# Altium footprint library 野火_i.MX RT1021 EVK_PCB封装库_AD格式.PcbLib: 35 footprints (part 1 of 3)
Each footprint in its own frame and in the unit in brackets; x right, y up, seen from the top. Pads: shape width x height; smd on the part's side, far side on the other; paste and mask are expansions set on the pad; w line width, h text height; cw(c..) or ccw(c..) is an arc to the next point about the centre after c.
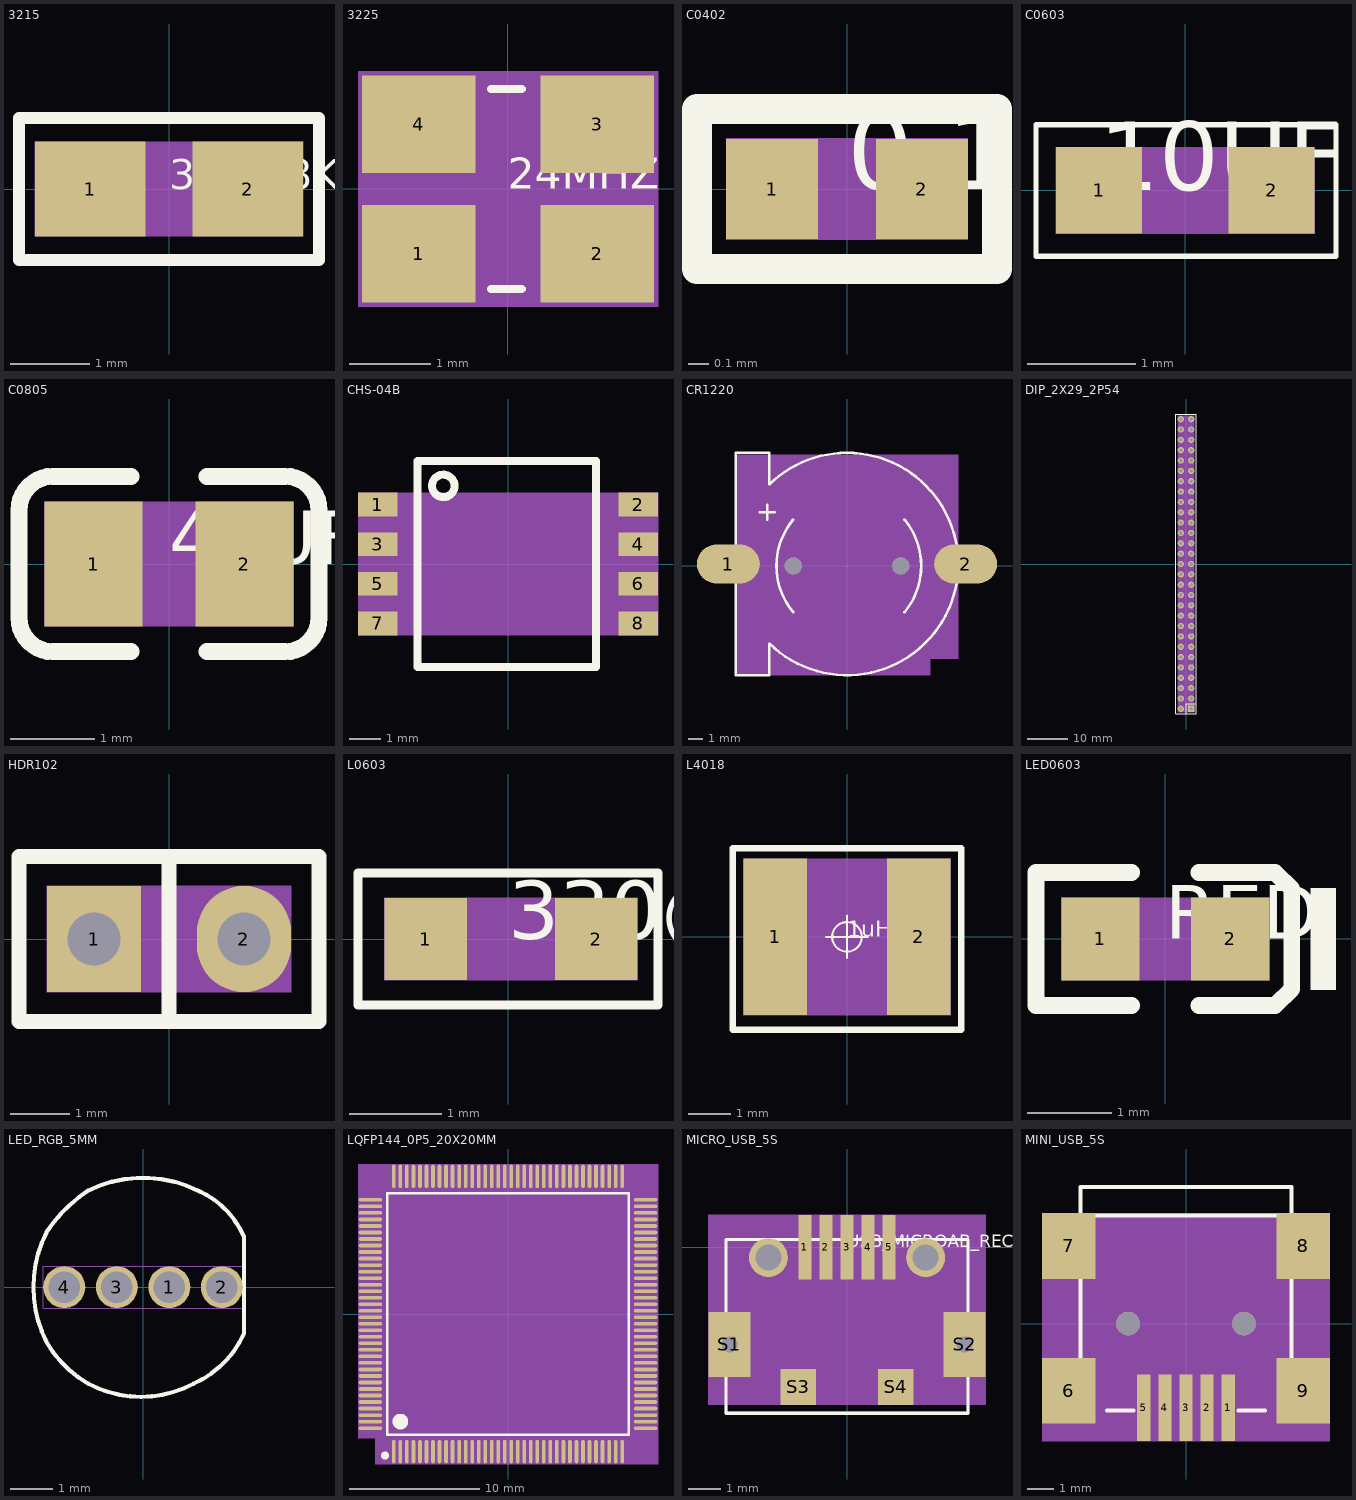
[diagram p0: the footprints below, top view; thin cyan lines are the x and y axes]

## 3215 [mm] "3215"
pads (2):
  rect 1.4x1.2 smd: 1(-1,0) 2(1,0)
Top Overlay:
  lines w0.15: -1.9,-0.9 1.9,-0.9 1.9,0.9 -1.9,0.9 -1.9,-0.9
  text "32.768KHZ" at 0,0 h0.38
Mechanical 6:
  text "1" at -1,0.152 h0.38
  text "2" at 1,0.152 h0.38
Mechanical 7:
  region: -1.7,-0.6 1.7,-0.6 1.7,0.6 -1.7,0.6
3D body: height 3.81, standoff 0, extent -1.7,-0.6 1.7,0.6

## 3225 [mil] "3225"
pads (4):
  rect 55.12x47.24 smd: 1(-43.3,-31.5) 2(43.31,-31.5) 3(43.31,31.49) 4(-43.3,31.49)
Top Overlay:
  lines w3.94: -8.3,-48.51 6.7,-48.51 ; -8.3,48.51 6.7,48.51
  text "24MHZ" at 0,0 h15
Mechanical 6:
  text "3" at 43.31,25.49 h15
  text "1" at -43.3,-37.5 h15
  text "4" at -43.3,25.49 h15
  text "2" at 43.31,-37.5 h15
Mechanical 7:
  region: -72.83,-57.09 72.84,-57.09 72.84,57.08 -72.83,57.08
3D body: height 150, standoff 0, extent -72.83,-57.09 72.84,57.08

## C0402 [mm] "C0402"
pads (2):
  rect 0.46x0.5 smd: 1(-0.375,0) 2(0.375,0)
Top Overlay:
  lines w0.15: -0.75,-0.4 -0.75,0.4 0.75,0.4 0.75,-0.4 -0.75,-0.4
  text "0.1UF" at 0,0 h0.38
Mechanical 6:
  text "1" at -0.375,0.152 h0.38
  text "2" at 0.375,0.152 h0.38
Mechanical 7:
  region: -0.605,-0.255 0.605,-0.255 0.605,0.255 -0.605,0.255
3D body: height 3.81, standoff 0, extent -0.605,-0.255 0.605,0.255

## C0603 [mil] "C0603"
pads (2):
  rect 31.5x31.5 smd: 1(-31.5,0) 2(31.49,0)
Top Overlay:
  lines w2: -54.5,-24 55,-24 55,24 -54.5,24 -54.5,-24
  text "10UF" at -31.5,0 h25
Mechanical 6:
  text "1" at -31.5,-10 h25
  text "2" at 31.49,-10 h25
Mechanical 7:
  region: -47.25,-15.75 47.24,-15.75 47.24,15.75 -47.25,15.75
3D body: height 150, standoff 0, extent -47.25,-15.75 47.24,15.75

## C0805 [mm] "C0805"
pads (2):
  rect 1.16x1.47 smd: 1(-0.89,0) 2(0.89,0)
Top Overlay:
  lines w0.2: -0.45,-1.035 -1.37,-1.035 cw(c-1.37,-0.635) -1.77,-0.635 -1.77,0.635 cw(c-1.37,0.635) -1.37,1.035 -0.45,1.035 ; 0.45,-1.035 1.37,-1.035 ccw(c1.37,-0.635) 1.77,-0.635 1.77,0.635 ccw(c1.37,0.635) 1.37,1.035 0.45,1.035
  text "47UF" at 0,0 h0.64
Mechanical 6:
  text "2" at 0.89,-0.254 h0.64
  text "1" at -0.89,-0.254 h0.64
Mechanical 7:
  region: -1.47,-0.735 1.47,-0.735 1.47,0.735 -1.47,0.735
3D body: height 3.81, standoff 0, extent -1.47,-0.735 1.47,0.735

## CHS-04B [mil] "CHS-04B"
pads (8):
  rect 50x30 smd: 1(-164.37,75) 2(164.37,75) 3(-164.37,25) 4(164.37,25) 5(-164.37,-25) 6(164.37,-25) 7(-164.37,-75) 8(164.37,-75)
Top Overlay:
  circle w10: c-81.69,98.62 r14.19
  lines w10: -114.37,-130.12 -114.37,130.12 111.22,130.12 111.22,-130.12 -114.37,-130.12
Mechanical 6:
  text "7" at -164.37,-65 h25
  text "6" at 164.37,-15 h25
  text "5" at -164.37,-15 h25
  text "8" at 164.37,-65 h25
  text "4" at 164.37,35 h25
  text "3" at -164.37,35 h25
  text "2" at 164.37,85 h25
  text "1" at -164.37,85 h25
Mechanical 7:
  region: -189.37,-89.96 189.37,-89.96 189.37,89.96 -189.37,89.96
3D body: height 150, standoff 0, extent -189.37,-89.96 189.37,89.96

## CR1220 [mil] "CR1220"
pads (4):
  oval 169.29x106.3 smd: 1(-320,5) 2(320,5)
  round 46 / inner round 60 / far side round 46 hole 46: " "(-145,0) " "(145,0)
Top Overlay:
  lines w7: -235,145 -195,145 ; -215,125 -215,165 ; -145.19,-124.77 cw(c5,0) -145.09,124.89 ; 155,-125 ccw(c5,0) 155.09,124.89 ; 298.2,-27.8 cw(c0,5) -209.62,-209.61 -210,-295 -300,-295 -300,5 -300,305 -210,305 -209.62,219.61 cw(c0,5.01) 0,305 cw(c0,5) 298.2,37.8
Mechanical 6:
  text "1" at -310,5 h25
  text "2" at 330,5 h25
Mechanical 7:
  region: -300,-295 225,-295 225,-250 300,-250 300,300 -300,300
3D body: height 150, standoff 0, extent -300,-295 300,300

## DIP_2X29_2P54 [mil] "DIP_2X29_2P54"
pads (58):
  rect 60x60 / inner round 60 / far side rect 60x60 hole 35.43: 1(50,-1400)
  round 60 hole 35.43: 2(-50,-1400) 3(50,-1300) 4(-50,-1300) 5(50,-1200) 6(-50,-1200) 7(50,-1100) 8(-50,-1100) 9(50,-1000) 10(-50,-1000) 11(50,-900) 12(-50,-900) 13(50,-800) 14(-50,-800) 15(50,-700) 16(-50,-700) 17(50,-600) 18(-50,-600) 19(50,-500) 20(-50,-500) 21(50,-400) 22(-50,-400) 23(50,-300) 24(-50,-300) 25(50,-200) 26(-50,-200) 27(50,-100) 28(-50,-100) 29(50,0) 30(-50,0) 31(50,100) 32(-50,100) 33(50,200) 34(-50,200) 35(50,300) 36(-50,300) 37(50,400) 38(-50,400) 39(50,500) 40(-50,500) 41(50,600) 42(-50,600) 43(50,700) 44(-50,700) 45(50,800) 46(-50,800) 47(50,900) 48(-50,900) 49(50,1000) 50(-50,1000) 51(50,1100) 52(-50,1100) 53(50,1200) 54(-50,1200) 55(50,1300) 56(-50,1300) 57(50,1400) 58(-50,1400)
Top Overlay:
  lines w12: 0,-1450 0,-1350 100,-1350 ; -100,-1450 -100,1450 100,1450 100,-1450 -100,-1450
Mechanical 6:
  text "1" at 60,-1400 h25
  text "3" at 60,-1300 h25
  text "5" at 60,-1200 h25
  text "7" at 60,-1100 h25
  text "9" at 60,-1000 h25
  text "11" at 70,-900 h25
  text "13" at 70,-800 h25
  text "15" at 70,-700 h25
  text "18" at -30,-600 h25
  text "16" at -30,-700 h25
  text "12" at -30,-900 h25
  text "8" at -40,-1100 h25
  text "58" at -30,1400 h25
  text "57" at 70,1400 h25
  text "47" at 70,900 h25
  text "14" at -30,-800 h25
  text "22" at -30,-400 h25
  text "21" at 70,-400 h25
  text "48" at -30,900 h25
  text "45" at 70,800 h25
  text "46" at -30,800 h25
  text "43" at 70,700 h25
  text "41" at 70,600 h25
  text "44" at -30,700 h25
  text "39" at 70,500 h25
  text "38" at -30,400 h25
  text "37" at 70,400 h25
  text "36" at -30,300 h25
  text "35" at 70,300 h25
  text "42" at -30,600 h25
  text "40" at -30,500 h25
  text "10" at -30,-1000 h25
  text "19" at 70,-500 h25
  text "17" at 70,-600 h25
  text "6" at -40,-1200 h25
  text "4" at -40,-1300 h25
  text "33" at 70,200 h25
  text "20" at -30,-500 h25
  text "23" at 70,-300 h25
  text "50" at -30,1000 h25
  text "53" at 70,1200 h25
  text "54" at -30,1200 h25
  text "51" at 70,1100 h25
  text "52" at -30,1100 h25
  text "49" at 70,1000 h25
  text "26" at -30,-200 h25
  text "32" at -30,100 h25
  text "34" at -30,200 h25
  text "31" at 70,100 h25
  text "29" at 70,0 h25
  text "28" at -30,-100 h25
  text "27" at 70,-100 h25
  text "24" at -30,-300 h25
  text "25" at 70,-200 h25
  text "30" at -30,0 h25
  text "2" at -40,-1400 h25
  text "55" at 70,1300 h25
  text "56" at -30,1300 h25
Mechanical 7:
  region: -81,-1431 81,-1431 81,1431 -81,1431
3D body: height 150, standoff 0, extent -81,-1431 81,1431

## HDR102 [mil] "HDR102"
pads (2):
  rect 62.99x70.87 / inner round 60 / far side rect 62.99x70.87 hole 35.43: 1(-50,0)
  oval 62.99x70.87 / inner round 60 / far side oval 62.99x70.87 hole 35.43: 2(50,0)
Top Overlay:
  lines w10: 0,-55.12 0,55.12 ; -100,-55.12 100,-55.12 100,55.12 -100,55.12 -100,-55.12
Mechanical 6:
  text "2" at 50,-10 h25
  text "1" at -50,-10 h25
Mechanical 7:
  region: -81.5,-35.43 81.5,-35.43 81.5,35.43 -81.5,35.43
3D body: height 150, standoff 0, extent -81.5,-35.43 81.5,35.43

## L0603 [mil] "L0603"
pads (2):
  rect 35x35 smd: 1(-35,0) 2(37.49,0)
Top Overlay:
  lines w3.94: -63.74,-28 -63.74,28 63.74,28 63.74,-28 -63.74,-28
  text "330@100MHz" at 0,0 h25
Mechanical 6:
  text "2" at 37.49,-10 h25
  text "1" at -35,-10 h25
Mechanical 7:
  region: -52.5,-17.5 54.99,-17.5 54.99,17.5 -52.5,17.5
3D body: height 150, standoff 0, extent -52.5,-17.5 54.99,17.5

## L4018 [mm] "L4018"
pads (2):
  rect 1.5x3.7 smd: 1(-1.7,0) 2(1.7,0)
Top Overlay:
  circle w0.05: c0,0 r0.35
  lines w0.05: -0.5,0 0.5,0 ; 0,-0.5 0,0.5
  lines w0.152: -2.7,-2.2 -2.7,2.1 2.7,2.1 2.7,-2.2 -2.7,-2.2
  text "1uH" at 0,0 h0.38
Mechanical 6:
  text "1" at -1.7,0.152 h0.38
  text "2" at 1.7,0.152 h0.38
Mechanical 7:
  region: -2.45,-1.85 2.45,-1.85 2.45,1.85 -2.45,1.85
3D body: height 3.81, standoff 0, extent -2.45,-1.85 2.45,1.85

## LED0603 [mil] "LED0603"
pads (2):
  rect 36.61x38.58 smd: 1(-30.31,0) 2(30.32,0)
Top Overlay:
  pour cut-out: 67.91,-23.62 79.73,-23.62 79.73,23.62 67.91,23.62
  lines w7.87: -15.75,-31.1 -60.43,-31.1 -60.43,31.1 -15.75,31.1 ; 15.75,-31.1 51.18,-31.1 59.06,-23.5 59.06,23.5 51.18,31.1 15.75,31.1
  text "RED" at 0,0 h25
Mechanical 6:
  text "1" at -20.31,0 h25
  text "2" at 40.32,0 h25
Mechanical 7:
  region: -48.62,-19.29 48.62,-19.29 48.62,19.29 -48.62,19.29
3D body: height 150, standoff 0, extent -48.62,-19.29 48.62,19.29

## LED_RGB_5MM [mm] "LED_RGB_5MM"
pads (4):
  round 1 / inner round 1.524 / far side round 1 hole 0.75: 1(0.625,0) 2(1.875,0) 3(-0.625,0) 4(-1.875,0)
Top Overlay:
  lines w0.1: -2.3,-1.3 ccw(c0.05,0.05) -1.3,-2.3 ccw(c-0.05,0.05) 1.2,-2.3 ccw(c0.25,-0.15) 2.4,-1.1 2.4,1.2 ccw(c0.45,0.35) 1.3,2.3 ccw(c0,-0.35) -1.3,2.3 ccw(c0.65,-0.65) -2.3,1.3 ccw(c0.3,0) -2.3,-1.3
Mechanical 6:
  text "3" at -0.879,0 h0.64
  text "2" at 1.621,0 h0.64
  text "1" at 0.371,0 h0.64
  text "4" at -2.129,0 h0.64
Mechanical 7:
  lines w0.025: -2.375,-0.5 2.375,-0.5 2.375,0.5 -2.375,0.5 -2.375,-0.5

## LQFP144_0P5_20X20MM [mil] "LQFP144_0P5_20X20MM"
pads (144):
  oval 11.02x70.87 smd: 1(-344.49,-415.35) 2(-324.8,-415.35) 3(-305.12,-415.35) 4(-285.43,-415.35) 5(-265.75,-415.35) 6(-246.06,-415.35) 7(-226.38,-415.35) 8(-206.69,-415.35) 9(-187.01,-415.35) 10(-167.32,-415.35) 11(-147.64,-415.35) 12(-127.95,-415.35) 13(-108.27,-415.35) 14(-88.58,-415.35) 15(-68.9,-415.35) 16(-49.21,-415.35) 17(-29.53,-415.35) 18(-9.84,-415.35) 19(9.84,-415.35) 20(29.53,-415.35) 21(49.21,-415.35) 22(68.9,-415.35) 23(88.58,-415.35) 24(108.27,-415.35) 25(127.95,-415.35) 26(147.64,-415.35) 27(167.32,-415.35) 28(187.01,-415.35) 29(206.69,-415.35) 30(226.38,-415.35) 31(246.06,-415.35) 32(265.75,-415.35) 33(285.43,-415.35) 34(305.12,-415.35) 35(324.8,-415.35) 36(344.49,-415.35) 73(344.49,415.35) 74(324.8,415.35) 75(305.12,415.35) 76(285.43,415.35) 77(265.75,415.35) 78(246.06,415.35) 79(226.38,415.35) 80(206.69,415.35) 81(187.01,415.35) 82(167.32,415.35) 83(147.64,415.35) 84(127.95,415.35) 85(108.27,415.35) 86(88.58,415.35) 87(68.9,415.35) 88(49.21,415.35) 89(29.53,415.35) 90(9.84,415.35) 91(-9.84,415.35) 92(-29.53,415.35) 93(-49.21,415.35) 94(-68.9,415.35) 95(-88.58,415.35) 96(-108.27,415.35) 97(-127.95,415.35) 98(-147.64,415.35) 99(-167.32,415.35) 100(-187.01,415.35) 101(-206.69,415.35) 102(-226.38,415.35) 103(-246.06,415.35) 104(-265.75,415.35) 105(-285.43,415.35) 106(-305.12,415.35) 107(-324.8,415.35) 108(-344.49,415.35)
  oval 70.87x11.02 smd: 37(415.35,-344.49) 38(415.35,-324.8) 39(415.35,-305.12) 40(415.35,-285.43) 41(415.35,-265.75) 42(415.35,-246.06) 43(415.35,-226.38) 44(415.35,-206.69) 45(415.35,-187.01) 46(415.35,-167.32) 47(415.35,-147.64) 48(415.35,-127.95) 49(415.35,-108.27) 50(415.35,-88.58) 51(415.35,-68.9) 52(415.35,-49.21) 53(415.35,-29.53) 54(415.35,-9.84) 55(415.35,9.84) 56(415.35,29.53) 57(415.35,49.21) 58(415.35,68.9) 59(415.35,88.58) 60(415.35,108.27) 61(415.35,127.95) 62(415.35,147.64) 63(415.35,167.32) 64(415.35,187.01) 65(415.35,206.69) 66(415.35,226.38) 67(415.35,246.06) 68(415.35,265.75) 69(415.35,285.43) 70(415.35,305.12) 71(415.35,324.8) 72(415.35,344.49) 109(-415.35,344.49) 110(-415.35,324.8) 111(-415.35,305.12) 112(-415.35,285.43) 113(-415.35,265.75) 114(-415.35,246.06) 115(-415.35,226.38) 116(-415.35,206.69) 117(-415.35,187.01) 118(-415.35,167.32) 119(-415.35,147.64) 120(-415.35,127.95) 121(-415.35,108.27) 122(-415.35,88.58) 123(-415.35,68.9) 124(-415.35,49.21) 125(-415.35,29.53) 126(-415.35,9.84) 127(-415.35,-9.84) 128(-415.35,-29.53) 129(-415.35,-49.21) 130(-415.35,-68.9) 131(-415.35,-88.58) 132(-415.35,-108.27) 133(-415.35,-127.95) 134(-415.35,-147.64) 135(-415.35,-167.32) 136(-415.35,-187.01) 137(-415.35,-206.69) 138(-415.35,-226.38) 139(-415.35,-246.06) 140(-415.35,-265.75) 141(-415.35,-285.43) 142(-415.35,-305.12) 143(-415.35,-324.8) 144(-415.35,-344.49)
Top Overlay:
  circle w23.62: c-324.8,-324.8 r11.81
  circle w11.81: c-371.06,-427.17 r5.9
  lines w7.87: -364.17,-364.17 364.17,-364.17 364.17,364.17 -364.17,364.17 -364.17,-364.17
Mechanical 6:
  text "104" at -295.75,415.35 h25
  text "112" at -445.35,285.43 h25
  text "77" at 245.75,415.35 h25
  text "144" at -445.35,-344.49 h25
  text "11" at -167.64,-415.35 h25
  text "20" at 9.53,-415.35 h25
  text "29" at 186.69,-415.35 h25
  text "128" at -445.35,-29.53 h25
  text "83" at 127.64,415.35 h25
  text "84" at 107.95,415.35 h25
  text "87" at 48.9,415.35 h25
  text "88" at 29.21,415.35 h25
  text "89" at 9.53,415.35 h25
  text "90" at -10.16,415.35 h25
  text "91" at -29.84,415.35 h25
  text "92" at -49.53,415.35 h25
  text "76" at 265.43,415.35 h25
  text "78" at 226.06,415.35 h25
  text "80" at 186.69,415.35 h25
  text "81" at 167.01,415.35 h25
  text "59" at 395.35,88.58 h25
  text "115" at -445.35,226.38 h25
  text "41" at 395.35,-265.75 h25
  text "66" at 395.35,226.38 h25
  text "61" at 395.35,127.95 h25
  text "86" at 68.58,415.35 h25
  text "102" at -256.38,415.35 h25
  text "134" at -445.35,-147.64 h25
  text "5" at -275.75,-415.35 h25
  text "39" at 395.35,-305.12 h25
  text "31" at 226.06,-415.35 h25
  text "114" at -445.35,246.06 h25
  text "55" at 395.35,9.84 h25
  text "69" at 395.35,285.43 h25
  text "73" at 324.49,415.35 h25
  text "79" at 206.38,415.35 h25
  text "105" at -315.43,415.35 h25
  text "101" at -236.69,415.35 h25
  text "8" at -216.69,-415.35 h25
  text "4" at -295.43,-415.35 h25
  text "125" at -445.35,29.53 h25
  text "9" at -197.01,-415.35 h25
  text "123" at -445.35,68.9 h25
  text "124" at -445.35,49.21 h25
  text "10" at -187.32,-415.35 h25
  text "12" at -147.95,-415.35 h25
  text "13" at -128.27,-415.35 h25
  text "14" at -108.58,-415.35 h25
  text "15" at -88.9,-415.35 h25
  text "16" at -69.21,-415.35 h25
  text "117" at -445.35,187.01 h25
  text "118" at -445.35,167.32 h25
  text "119" at -445.35,147.64 h25
  text "120" at -445.35,127.95 h25
  text "121" at -445.35,108.27 h25
  text "122" at -445.35,88.58 h25
  text "17" at -49.53,-415.35 h25
  text "18" at -29.84,-415.35 h25
  text "116" at -445.35,206.69 h25
  text "3" at -315.12,-415.35 h25
  text "126" at -445.35,9.84 h25
  text "127" at -445.35,-9.84 h25
  text "7" at -236.38,-415.35 h25
  text "1" at -354.49,-415.35 h25
  text "2" at -334.8,-415.35 h25
  text "131" at -445.35,-88.58 h25
  text "132" at -445.35,-108.27 h25
  text "133" at -445.35,-127.95 h25
  text "136" at -445.35,-187.01 h25
  text "137" at -445.35,-206.69 h25
  text "138" at -445.35,-226.38 h25
  text "139" at -445.35,-246.06 h25
  text "140" at -445.35,-265.75 h25
  text "129" at -445.35,-49.21 h25
  text "130" at -445.35,-68.9 h25
  text "143" at -445.35,-324.8 h25
  text "141" at -445.35,-285.43 h25
  text "142" at -445.35,-305.12 h25
  text "42" at 395.35,-246.06 h25
  text "43" at 395.35,-226.38 h25
  text "45" at 395.35,-187.01 h25
  text "46" at 395.35,-167.32 h25
  text "48" at 395.35,-127.95 h25
  text "47" at 395.35,-147.64 h25
  text "50" at 395.35,-88.58 h25
  text "54" at 395.35,-9.84 h25
  text "53" at 395.35,-29.53 h25
  text "63" at 395.35,167.32 h25
  text "62" at 395.35,147.64 h25
  text "49" at 395.35,-108.27 h25
  text "36" at 324.49,-415.35 h25
  text "37" at 395.35,-344.49 h25
  text "58" at 395.35,68.9 h25
  text "57" at 395.35,49.21 h25
  text "67" at 395.35,246.06 h25
  text "68" at 395.35,265.75 h25
  text "56" at 395.35,29.53 h25
  text "72" at 395.35,344.49 h25
  text "65" at 395.35,206.69 h25
  text "38" at 395.35,-324.8 h25
  text "34" at 285.12,-415.35 h25
  text "52" at 395.35,-49.21 h25
  text "111" at -445.35,305.12 h25
  text "110" at -445.35,324.8 h25
  text "109" at -445.35,344.49 h25
  text "74" at 304.8,415.35 h25
  text "75" at 285.12,415.35 h25
  text "82" at 147.32,415.35 h25
  text "108" at -374.49,415.35 h25
  text "71" at 395.35,324.8 h25
  text "6" at -256.06,-415.35 h25
  text "135" at -445.35,-167.32 h25
  text "40" at 395.35,-285.43 h25
  text "51" at 395.35,-68.9 h25
  text "60" at 395.35,108.27 h25
  text "113" at -445.35,265.75 h25
  text "103" at -276.06,415.35 h25
  text "35" at 304.8,-415.35 h25
  text "64" at 395.35,187.01 h25
  text "70" at 395.35,305.12 h25
  text "85" at 88.27,415.35 h25
  text "25" at 107.95,-415.35 h25
  text "26" at 127.64,-415.35 h25
  text "33" at 265.43,-415.35 h25
  text "19" at -10.16,-415.35 h25
  text "32" at 245.75,-415.35 h25
  text "21" at 29.21,-415.35 h25
  text "30" at 206.38,-415.35 h25
  text "22" at 48.9,-415.35 h25
  text "28" at 167.01,-415.35 h25
  text "23" at 68.58,-415.35 h25
  text "27" at 147.32,-415.35 h25
  text "24" at 88.27,-415.35 h25
  text "100" at -217.01,415.35 h25
  text "95" at -108.58,415.35 h25
  text "93" at -69.21,415.35 h25
  text "94" at -88.9,415.35 h25
  text "96" at -128.27,415.35 h25
  text "99" at -187.32,415.35 h25
  text "98" at -167.64,415.35 h25
  text "107" at -354.8,415.35 h25
  text "106" at -335.12,415.35 h25
  text "97" at -147.95,415.35 h25
  text "44" at 395.35,-206.69 h25
Mechanical 7:
  region: -400,-452.79 452.79,-452.79 452.79,452.79 -452.79,452.79 -452.79,-375 -400,-375
3D body: height 150, standoff 0, extent -452.79,-452.79 452.79,452.79

## MICRO_USB_5S [mm] "MICRO_USB_5S"
pads (11):
  rect 0.4x2 smd: 1(-1.3,0) 2(-0.65,0) 3(0,0) 4(0.65,0) 5(1.3,0)
  round 1.2 / inner round 1.524 / far side round 1.2 hole 0.8: " "(-2.425,-0.32) " "(2.425,-0.32)
  rect 1.3x2 / inner round 1.524 / far side rect 1.3x2 hole 0.5: S1(-3.625,-3) S2(3.625,-3)
  rect 1.1x1.1 smd: S3(-1.5,-4.31) S4(1.5,-4.31)
Top Overlay:
  lines w0.1: -3.73,-5.12 -3.73,0.235 3.73,0.235 3.73,-5.12 -3.73,-5.12
  text "USB_MICROAB_RECEPTACLE" at 0,0 h0.38
Mechanical 6:
  text "1" at -1.148,0 h0.38
  text "S3" at -1.195,-4.31 h0.38
  text "S4" at 1.805,-4.31 h0.38
  text "S2" at 3.93,-3 h0.38
  text "S1" at -3.32,-3 h0.38
  text "4" at 0.802,0 h0.38
  text "3" at 0.152,0 h0.38
  text "2" at -0.498,0 h0.38
  text "5" at 1.452,0 h0.38
Mechanical 7:
  region: -4.275,-4.86 4.275,-4.86 4.275,1 -4.275,1
Mechanical 8:
  lines w0.1: -3.73,-5.12 -3.73,0.235 3.73,0.235 3.73,-5.12 -3.73,-5.12
3D body: height 3.81, standoff 0, extent -4.275,-4.86 4.275,1

## MINI_USB_5S [mil] "MINI_USB_5S"
pads (11):
  rect 20x100 smd: 1(62.99,-125.98) 2(31.5,-125.98) 3(0,-125.98) 4(-31.5,-125.98) 5(-62.99,-125.98)
  rect 80x98.43 smd: 6(-175.2,-100.39) 7(-175.2,116.14) 8(175.2,116.14) 9(175.2,-100.39)
  round 35.43 / inner round 60 / far side round 35.43 hole 35.43: " "(-86.61,0) " "(86.61,0)
Top Overlay:
  lines w6: -157.48,-59.06 -157.48,74.8 ; -157.48,157.48 -157.48,204.72 157.48,204.72 157.48,157.48 ; -157.48,161.42 157.48,161.42 ; -118.11,-129.92 -78.74,-129.92 ; 78.74,-129.92 118.11,-129.92 ; 157.48,-59.06 157.48,74.8
Mechanical 6:
  text "8" at 185.2,116.14 h25
  text "9" at 185.2,-100.39 h25
  text "7" at -165.2,116.14 h25
  text "6" at -165.2,-100.39 h25
  text "1" at 72.99,-125.98 h25
  text "3" at 10,-125.98 h25
  text "2" at 41.5,-125.98 h25
  text "4" at -21.5,-125.98 h25
  text "5" at -52.99,-125.98 h25
Mechanical 7:
  region: -215.2,-175.98 215.2,-175.98 215.2,165.35 -215.2,165.35
3D body: height 150, standoff 0, extent -215.2,-175.98 215.2,165.35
